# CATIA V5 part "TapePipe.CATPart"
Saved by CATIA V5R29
Part number: TapePipe
Source: Unknown
Bounding box of the stored display mesh (mm): x -50 to 200, y -20 to 100, z -25 to 25
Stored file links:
  C:\가치같이\SmartFactory_BoxErectorConveyor\Boxing(under)\TapePipe.CATPart
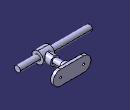
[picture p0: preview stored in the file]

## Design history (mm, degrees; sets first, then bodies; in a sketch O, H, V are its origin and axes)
Body1 (main body)
  Solid1 "PartBody": solid without history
